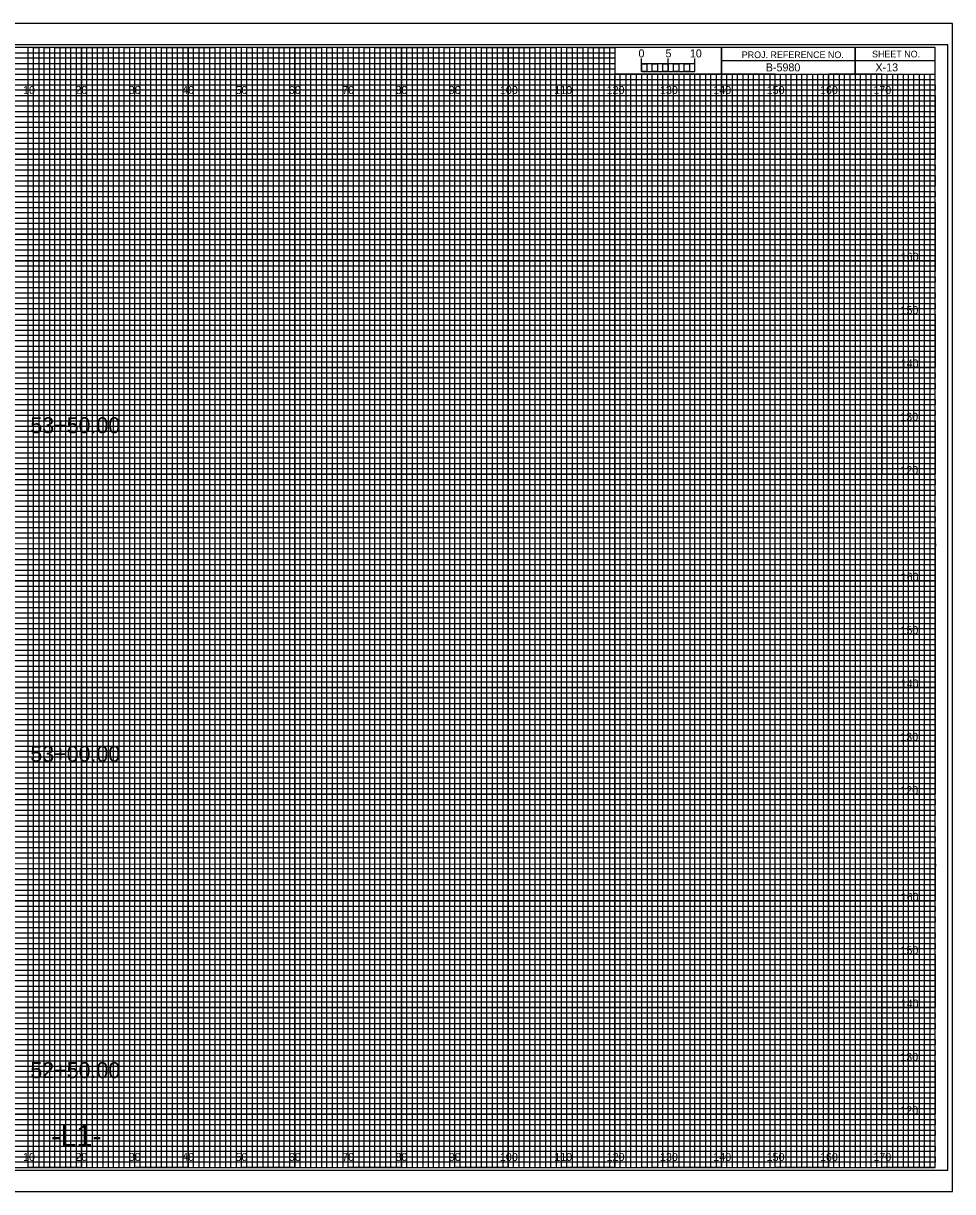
# Model space of a CAD drawing. Extents: x -13 to 323, y -5 to 3294.
# Drawn here: x 149.1 to 323.3, y 2635.5 to 2854.5 of the extents above; entities that cross this region are included whole.
import ezdxf

# ---------------------------------------------------------------- set-up
doc = ezdxf.new("R2010")
doc.units = 0
for name, color, linetype in [('Prop XS Alignment Label', 7, 'Continuous'), ('Prop XS Bar Scale Labels', 7, 'Continuous'), ('Prop XS Elevation Labels', 7, 'Continuous'), ('Prop XS Offset Labels', 7, 'Continuous'), ('Prop XS Project Number', 7, 'Continuous'), ('Prop XS Sheet Number', 7, 'Continuous'), ('Prop XS Station Labels', 7, 'Continuous'), ('Scratch_Level_0', 7, 'Continuous'), ('Sheet Cross Section CELL', 7, 'Continuous'), ('Sheet Cross Section Grid Major CELL', 7, 'Continuous'), ('Sheet Cross Section Grid Middle CELL', 7, 'Continuous'), ('Sheet Cross Section Grid Minor 1 CELL', 7, 'Continuous'), ('Sheet Cross Section Grid Minor 2 CELL', 7, 'Continuous'), ('Sheet Cross Section Scale CELL', 7, 'Continuous'), ('Sheet Cutting Line CELL', 7, 'Continuous'), ('Sheet DOT Grid CELL', 7, 'Continuous'), ('Sheet Plot Border Inside CELL', 7, 'Continuous'), ('Sheet Plot Border Outside CELL', 7, 'Continuous')]:
    doc.layers.add(name, color=color, linetype=linetype)

msp = doc.modelspace()

# ---------------------------------------------------------------- linework, layer by layer
at = {"layer": 'Scratch_Level_0'}
for points in [[(10, 2815), (310, 2815), (310, 2770), (10, 2770)], [(10, 2750), (320, 2750), (320, 2710), (10, 2710)], [(10, 2690), (310, 2690), (310, 2650), (10, 2650)]]:
    msp.add_lwpolyline(points, close=True, dxfattribs=at)
at = {"layer": 'Sheet Cross Section CELL'}
for p, q in [((305, 2850), (305, 2845)), ((305, 2845), (305, 2850)), ((280, 2847.5), (280, 2845)), ((320, 2847.49), (280, 2847.49)), ((280, 2845), (320, 2845))]:
    msp.add_line(p, q, dxfattribs=at)
for points in [[(320, 2850), (0, 2850), (0, 2640), (320, 2640)], [(280, 2850), (260, 2850), (260, 2845.03), (280, 2845.03)], [(320, 2850), (280, 2850), (280, 2845), (320, 2845)]]:
    msp.add_lwpolyline(points, close=True, dxfattribs=at)
at = {"layer": 'Sheet Cross Section Grid Major CELL'}
for p, q in [((150, 2850), (140, 2850)), ((150, 2640), (150, 2850)), ((170, 2850), (160, 2850)), ((160, 2850), (160, 2640)), ((170, 2640), (170, 2850)), ((190, 2850), (180, 2850)), ((180, 2850), (180, 2640)), ((190, 2640), (190, 2850)), ((210, 2850), (200, 2850)), ((200, 2850), (200, 2640)), ((210, 2640), (210, 2850)), ((230, 2850), (220, 2850)), ((220, 2850), (220, 2640)), ((230, 2640), (230, 2850)), ((250, 2850), (240, 2850)), ((240, 2850), (240, 2640)), ((250, 2640), (250, 2850)), ((260, 2850), (260, 2640)), ((270, 2640), (270, 2845)), ((290, 2845), (280, 2845)), ((280, 2845), (280, 2640)), ((290, 2640), (290, 2845)), ((310, 2845), (300, 2845)), ((300, 2845), (300, 2640)), ((310, 2640), (310, 2845)), ((160, 2640), (150, 2640)), ((180, 2640), (170, 2640)), ((200, 2640), (190, 2640)), ((220, 2640), (210, 2640)), ((240, 2640), (230, 2640)), ((260, 2640), (250, 2640)), ((280, 2640), (270, 2640)), ((300, 2640), (290, 2640)), ((320, 2640), (310, 2640)), ((320, 2640), (320, 2640))]:
    msp.add_line(p, q, dxfattribs=at)
for points in [[(0, 2840), (320, 2840), (320, 2830), (0, 2830)], [(0, 2820), (320, 2820), (320, 2810), (0, 2810)], [(0, 2800), (320, 2800), (320, 2790), (0, 2790)], [(0, 2780), (320, 2780), (320, 2770), (0, 2770)], [(0, 2760), (320, 2760), (320, 2750), (0, 2750)], [(0, 2740), (320, 2740), (320, 2730), (0, 2730)], [(0, 2720), (320, 2720), (320, 2710), (0, 2710)], [(0, 2700), (320, 2700), (320, 2690), (0, 2690)], [(0, 2680), (320, 2680), (320, 2670), (0, 2670)], [(0, 2660), (320, 2660), (320, 2650), (0, 2650)]]:
    msp.add_lwpolyline(points, dxfattribs=at)
at = {"layer": 'Sheet Cross Section Grid Middle CELL'}
for points in [[(145, 2640), (155, 2640), (155, 2850), (165, 2850), (165, 2640), (175, 2640), (175, 2850), (185, 2850), (185, 2640), (195, 2640), (195, 2850), (205, 2850), (205, 2640), (215, 2640), (215, 2850), (225, 2850), (225, 2640), (235, 2640), (235, 2850), (245, 2850), (245, 2640), (255, 2640), (255, 2850), (259.93, 2850), (260, 2850), (260, 2845), (264.99, 2845), (264.99, 2640), (275, 2640), (275, 2845), (285, 2845), (285, 2640), (295, 2640), (295, 2845), (305, 2845), (305, 2640), (315, 2640), (315, 2845)], [(0, 2845), (275, 2845)], [(0, 2825), (320, 2825), (320, 2835), (0, 2835)], [(0, 2805), (320, 2805), (320, 2815), (0, 2815)], [(0, 2785), (320, 2785), (320, 2795), (0, 2795)], [(0, 2765), (320, 2765), (320, 2775), (0, 2775)], [(0, 2745), (320, 2745), (320, 2755), (0, 2755)], [(0, 2725), (320, 2725), (320, 2735), (0, 2735)], [(0, 2705), (320, 2705), (320, 2715), (0, 2715)], [(0, 2685), (320, 2685), (320, 2695), (0, 2695)], [(0, 2665), (320, 2665), (320, 2675), (0, 2675)], [(0, 2645), (320, 2645), (320, 2655), (0, 2655)]]:
    msp.add_lwpolyline(points, dxfattribs=at)
at = {"layer": 'Sheet Cross Section Grid Minor 1 CELL'}
for p, q in [((0, 2849), (260, 2849)), ((260, 2847.98), (0, 2847.98)), ((0, 2847), (260, 2847)), ((260, 2849), (260, 2847.98)), ((260, 2847), (260, 2845.89)), ((260, 2845.89), (0, 2845.89)), ((0, 2844), (320, 2844))]:
    msp.add_line(p, q, dxfattribs=at)
for points in [[(0, 2843), (270, 2843), (320, 2843), (320, 2842), (0, 2842)], [(0, 2841), (320, 2841), (320, 2839), (0, 2839)], [(0, 2838), (320, 2838), (320, 2837), (0, 2836.98)], [(0, 2836), (320, 2836), (320, 2834), (0, 2834)], [(0, 2833), (320, 2833), (320, 2832), (0, 2832)], [(0, 2831), (320, 2831), (320, 2829), (0, 2829)], [(0, 2828), (320, 2828), (320, 2827), (0, 2827)], [(0, 2826), (320, 2826), (320, 2824), (0, 2824)], [(0, 2823), (320, 2823), (320, 2822), (0, 2822)], [(0, 2821), (320, 2821), (320, 2819), (0, 2819)], [(0, 2818), (320, 2818), (320, 2817), (0, 2817)], [(0, 2816), (320, 2816), (320, 2813.95), (320, 2813), (320, 2812), (0, 2812)], [(0, 2814), (320, 2814), (320, 2813), (0, 2813)], [(0, 2811), (320, 2811), (320, 2809), (0, 2809.03)], [(0, 2809.03), (320, 2809), (320, 2808), (0, 2808)], [(0, 2807), (320, 2807), (320, 2806), (0, 2806)], [(0, 2804), (320, 2804), (320, 2803), (0, 2803)], [(0, 2802), (320, 2802), (320, 2801), (0, 2801)], [(-0.07, 2798.89), (320, 2798.89), (320, 2797.88), (-0.07, 2797.88)], [(0, 2797), (320, 2797), (320, 2796), (0, 2796)], [(0, 2794), (320, 2794), (320, 2793), (0, 2793)], [(0, 2792), (320, 2792), (320, 2791), (0, 2791)], [(0, 2789), (320, 2789), (320, 2788), (0, 2788)], [(0, 2787), (320, 2787), (320, 2786), (0, 2786)], [(0, 2784), (320, 2784), (320, 2783), (0, 2783)], [(0, 2782), (320, 2782), (320, 2781), (0, 2781)], [(0, 2779), (320, 2779), (319.99, 2777.98), (0, 2778)], [(0, 2777), (320, 2777), (320, 2776), (0, 2776)], [(0, 2774), (320, 2774), (320, 2773), (0, 2773)], [(0, 2772), (320, 2772), (320, 2771), (0, 2771)], [(0, 2769), (320, 2769), (320, 2768), (0, 2768)], [(0, 2767), (320, 2767), (320, 2766), (0, 2766)], [(0, 2764), (320, 2764), (320, 2763), (0, 2763)], [(0, 2762), (320, 2762), (320, 2761), (0, 2761)], [(0, 2759), (320, 2759), (320, 2758), (0, 2758)], [(0, 2756.99), (320.07, 2756.91), (320, 2756), (0, 2756)], [(0, 2754), (320, 2754), (320, 2753), (0, 2753)], [(0, 2752), (320, 2752), (320, 2751), (0, 2751)], [(0, 2749), (320, 2749), (320, 2748), (0, 2748)], [(0, 2747), (320, 2747), (320, 2746), (0, 2746)], [(0, 2744), (320, 2744), (320, 2743), (0, 2743)], [(0, 2742), (320, 2742), (320, 2741), (0, 2741)], [(0, 2739), (320, 2739), (320, 2738), (0, 2738)], [(0, 2737), (320, 2737), (320, 2736), (0, 2736)], [(0, 2734), (320, 2734), (320, 2733), (0, 2733)], [(0, 2732), (320, 2732), (320, 2731), (0, 2731)], [(0, 2729), (320, 2729), (320, 2728), (0, 2728)], [(0, 2727), (320, 2727), (320, 2726), (0, 2726)], [(0, 2724), (320, 2724), (320, 2723), (0, 2723)], [(0, 2722), (320, 2722), (320, 2721), (0, 2721)], [(0, 2719), (320, 2719), (319.99, 2717.98), (0, 2718)], [(0, 2717), (320, 2717), (320, 2716), (0, 2716)], [(0, 2714), (320, 2714), (320, 2713), (0, 2713)], [(0, 2712), (320, 2712), (320, 2711), (0, 2711)], [(0, 2709), (320, 2709), (320, 2708), (0, 2708)], [(0, 2707), (320, 2707), (320, 2706), (0, 2706)], [(0, 2704), (320, 2704), (320, 2703), (0, 2703)], [(0, 2702), (320, 2702), (320, 2701), (0, 2701)], [(0, 2699), (320, 2699), (320, 2698), (0, 2698)], [(0, 2696.99), (320.07, 2696.91), (320, 2696), (0, 2696)], [(0, 2694), (320, 2694), (320, 2693), (0, 2693)], [(0, 2692), (320, 2692), (320, 2691), (0, 2691)], [(0, 2689), (320, 2689), (320, 2688), (0, 2688)], [(0, 2687), (320, 2687), (320, 2686), (0, 2686)], [(0, 2684), (320, 2684), (320, 2683), (0, 2683)], [(0, 2682), (320, 2682), (320, 2681), (0, 2681)], [(0, 2679), (320, 2679), (320, 2678), (0, 2678)], [(0, 2677), (320, 2677), (320, 2676), (0, 2676)], [(0, 2674), (320, 2674), (320, 2673), (0, 2673)], [(0, 2672), (320, 2672), (320, 2671), (0, 2671)], [(0, 2669), (320, 2669), (320, 2668), (0, 2668)], [(0, 2667), (320, 2667), (320, 2666), (0, 2666)], [(0, 2664), (320, 2664), (320, 2663), (0, 2663)], [(0, 2662), (320, 2662), (320, 2661), (0, 2661)], [(0, 2659), (320, 2659), (320, 2658), (0, 2658)], [(0, 2657), (320, 2657), (320, 2656), (0, 2656)], [(0, 2654), (320, 2654), (320, 2653), (0, 2653)], [(0, 2652), (320, 2652), (320, 2651), (0, 2651)], [(0, 2649), (320, 2649), (320, 2648), (0, 2648)], [(0, 2647), (320, 2647), (320, 2646), (0, 2646)], [(0, 2644), (320, 2644), (320, 2643), (0, 2643)], [(0, 2642), (320, 2642), (320, 2641), (0, 2641)]]:
    msp.add_lwpolyline(points, dxfattribs=at)
at = {"layer": 'Sheet Cross Section Grid Minor 2 CELL'}
for p, q in [((267, 2845), (266.01, 2845)), ((266.01, 2845), (266.01, 2640)), ((267, 2640), (267, 2845)), ((269, 2845), (268, 2845)), ((268, 2845), (268, 2640)), ((269, 2640), (269, 2845)), ((266.01, 2640), (265, 2640)), ((268, 2640), (267, 2640))]:
    msp.add_line(p, q, dxfattribs=at)
for points in [[(150, 2640), (151, 2640), (151, 2850), (152, 2850), (152, 2640)], [(152, 2640), (153, 2640), (153, 2850), (154, 2850), (154, 2640)], [(155, 2640), (156, 2640), (156, 2850), (157, 2850), (157, 2640)], [(157, 2640), (158, 2640), (158, 2850), (159, 2850), (159, 2640)], [(160, 2640), (161, 2640), (161, 2850), (162, 2850), (162, 2640)], [(162, 2640), (163, 2640), (163, 2850), (164, 2850), (164, 2640)], [(165, 2640), (166, 2640), (166, 2850), (167, 2850), (167, 2640)], [(167, 2640), (168, 2640), (168, 2850), (169, 2850), (169, 2640)], [(170, 2640), (171, 2640), (171, 2850), (172, 2850), (172, 2640)], [(172, 2640), (173, 2640), (173, 2850), (174, 2850), (174, 2640)], [(175, 2640), (176, 2640), (176, 2850), (177, 2850), (177, 2640)], [(177, 2640), (178, 2640), (178, 2850), (179, 2850), (179, 2640)], [(180, 2640), (181, 2640), (181, 2850), (182, 2850), (182, 2640)], [(182, 2640), (183, 2640), (183, 2850), (184, 2850), (184, 2640)], [(185, 2640), (186, 2640), (186, 2850), (187, 2850), (187, 2640)], [(187, 2640), (188, 2640), (188, 2850), (189, 2850), (189, 2640)], [(190, 2640), (191, 2640), (191, 2850), (192, 2850), (192, 2640)], [(192, 2640), (193, 2640), (193, 2850), (194, 2850), (194, 2640)], [(195, 2640), (196, 2640), (196, 2850), (197, 2850), (197, 2640)], [(197, 2640), (198, 2640), (198, 2850), (199, 2850), (199, 2640)], [(200, 2640), (201, 2640), (201, 2850), (202, 2850), (202, 2640)], [(202, 2640), (203, 2640), (203, 2850), (204, 2850), (204, 2640)], [(205, 2640), (206, 2640), (206, 2850), (207, 2850), (207, 2640)], [(207, 2640), (208, 2640), (208, 2850), (209, 2850), (209, 2640)], [(210, 2640), (211, 2640), (211, 2850), (212, 2850), (212, 2640)], [(212, 2640), (213, 2640), (213, 2850), (214, 2850), (214, 2640)], [(215, 2640), (216, 2640), (216, 2850), (217, 2850), (217, 2640)], [(217, 2640), (218, 2640), (218, 2850), (219, 2850), (219, 2640)], [(220, 2640), (221, 2640), (221, 2850), (222, 2850), (222, 2640)], [(222, 2640), (223, 2640), (223, 2850), (224, 2850), (224, 2640)], [(225, 2640), (226, 2640), (226, 2850), (227, 2850), (227, 2640)], [(227, 2640), (228, 2640), (228, 2850), (229, 2850), (229, 2640)], [(230, 2640), (231, 2640), (231, 2850), (232, 2850), (232, 2640)], [(232, 2640), (233, 2640), (233, 2850), (234, 2850), (234, 2640)], [(235, 2640), (236, 2640), (236, 2850), (237, 2850), (237, 2640)], [(237, 2640), (238, 2640), (238, 2850), (239, 2850), (239, 2640)], [(240, 2640), (241, 2640), (241, 2850), (242, 2850), (242, 2640)], [(242, 2640), (243, 2640), (243, 2850), (244, 2850), (244, 2640)], [(245, 2640), (246, 2640), (246, 2850), (247, 2850), (247, 2640)], [(247, 2640), (248, 2640), (248, 2850), (249, 2850), (249, 2640)], [(250, 2640), (251, 2640), (251, 2850), (252, 2850), (252, 2640)], [(252, 2640), (253, 2640), (253, 2850), (254, 2850), (254, 2640)], [(255, 2640), (256, 2640), (256, 2850), (257, 2850), (257, 2640)], [(257, 2640), (258, 2640), (258, 2850), (259, 2850), (259, 2640)], [(260, 2640), (261, 2640), (261, 2845), (262.02, 2845), (262.02, 2640)], [(262, 2640), (263, 2640), (263, 2845), (263.99, 2845), (263.99, 2640)], [(270, 2640), (270.98, 2640), (270.98, 2845), (272, 2845), (272, 2640)], [(272, 2640), (273, 2640), (273, 2845), (274.05, 2845), (274.05, 2640)], [(275, 2640), (276, 2640), (276, 2845), (277, 2845), (277, 2640)], [(277, 2640), (278, 2640), (278, 2845), (279, 2845), (279, 2640)], [(280, 2640), (281, 2640), (281, 2845), (282, 2845), (282, 2640)], [(282, 2640), (283, 2640), (283, 2845), (284, 2845), (284, 2640)], [(285, 2640), (286, 2640), (286, 2845), (287, 2845), (287, 2640)], [(287, 2640), (288, 2640), (288, 2845), (289, 2845), (289, 2640)], [(290, 2640), (291, 2640), (291, 2845), (292, 2845), (292, 2640)], [(292, 2640), (293, 2640), (293, 2845), (294, 2845), (294, 2640)], [(295, 2640), (296, 2640), (296, 2845), (297, 2845), (297, 2640)], [(297, 2640), (298, 2640), (298, 2845), (299, 2845), (299, 2640)], [(300, 2640), (301, 2640), (301, 2845), (302, 2845), (302, 2640)], [(302, 2640), (303, 2640), (303, 2845), (304, 2845), (304, 2640)], [(305, 2640), (306, 2640), (306, 2845), (307, 2845), (307, 2640)], [(307, 2640), (308, 2640), (308, 2845), (309, 2845), (309, 2640)], [(310, 2640), (311, 2640), (311, 2845), (312, 2845), (312, 2640)], [(312, 2640), (313, 2640), (313, 2845), (314, 2845), (314, 2640)], [(315, 2640), (316, 2640), (316, 2845), (317, 2845), (317, 2640)], [(317, 2640), (318, 2640), (318, 2845), (319, 2845), (319, 2640)]]:
    msp.add_lwpolyline(points, dxfattribs=at)
at = {"layer": 'Sheet Cross Section Scale CELL'}
for p, q in [((265, 2845.49), (265, 2847.9)), ((265, 2846.9), (265, 2847.9)), ((270, 2845.49), (270, 2847.9)), ((275, 2845.49), (275, 2847.9)), ((275, 2846.9), (275, 2847.9))]:
    msp.add_line(p, q, dxfattribs=at)
for points in [[(275, 2846.9), (265, 2846.9), (265, 2845.49), (275, 2845.49)], [(265, 2846.9), (266, 2846.9), (266, 2845.49), (265, 2845.49)], [(267, 2846.9), (268, 2846.9), (268, 2845.49), (267, 2845.49)], [(269, 2846.9), (270, 2846.9), (270, 2845.49), (269, 2845.49)], [(271, 2846.9), (272, 2846.9), (272, 2845.49), (271, 2845.49)], [(273, 2846.9), (274, 2846.9), (274, 2845.49), (273, 2845.49)]]:
    msp.add_lwpolyline(points, close=True, dxfattribs=at)
at = {"layer": 'Sheet Cutting Line CELL'}
for p, q in [((323.3, 2854.5), (-13.4, 2854.5)), ((-13.4, 2635.5), (323.3, 2635.5))]:
    msp.add_line(p, q, dxfattribs=at)
at = {"layer": 'Sheet DOT Grid CELL'}
for p, q in [((150, 2640), (150, 2850)), ((160, 2640), (160, 2850)), ((170, 2640), (170, 2850)), ((180, 2640), (180, 2850)), ((190, 2640), (190, 2850)), ((200, 2640), (200, 2850)), ((210, 2640), (210, 2850)), ((220, 2640), (220, 2850)), ((230, 2640), (230, 2850)), ((240, 2640), (240, 2850)), ((250, 2640), (250, 2850)), ((260, 2640), (260, 2844.69)), ((270, 2640), (270, 2844.69)), ((280, 2640), (280, 2844.69)), ((290, 2640), (290, 2844.69)), ((300, 2640), (300, 2844.69)), ((310, 2640), (310, 2844.69)), ((0, 2840), (320, 2840)), ((0, 2830), (320, 2830)), ((0, 2820), (320, 2820)), ((0, 2810), (320, 2810)), ((0, 2800), (320, 2800)), ((0, 2790), (320, 2790)), ((0, 2780), (320, 2780)), ((0, 2770), (320, 2770)), ((0, 2760), (320, 2760)), ((0, 2750), (320, 2750)), ((0, 2740), (320, 2740)), ((0, 2730), (320, 2730)), ((0, 2720), (320, 2720)), ((0, 2710), (320, 2710)), ((0, 2700), (320, 2700)), ((0, 2690), (320, 2690)), ((0, 2680), (320, 2680)), ((0, 2670), (320, 2670)), ((0, 2660), (320, 2660)), ((0, 2650), (320, 2650))]:
    msp.add_line(p, q, dxfattribs=at)
at = {"layer": 'Sheet Plot Border Inside CELL'}
msp.add_lwpolyline([(-10.8, 2639.5), (322.4, 2639.5), (322.4, 2850.5), (-10.8, 2850.5)], close=True, dxfattribs=at)
at = {"layer": 'Sheet Plot Border Outside CELL'}
msp.add_lwpolyline([(-13.4, 2635.5), (323.3, 2635.5), (323.3, 2854.5), (-13.4, 2854.5)], close=True, dxfattribs=at)

# ---------------------------------------------------------------- texts
at = {"layer": 'Prop XS Alignment Label'}
msp.add_text('-L1-', height=4, dxfattribs=at).set_placement((154.28, 2644))
at = {"layer": 'Prop XS Bar Scale Labels'}
for s, p in [('5', (269.47, 2848.12)), ('10', (274.04, 2848.12))]:
    msp.add_text(s, height=1.5, dxfattribs=at).set_placement(p)
at = {"layer": 'Prop XS Elevation Labels'}
for s, p in [('160', (313.57, 2810)), ('150', (313.52, 2800)), ('140', (313.57, 2790)), ('130', (313.49, 2780)), ('120', (313.5, 2770)), ('160', (313.57, 2750)), ('150', (313.52, 2740)), ('140', (313.57, 2730)), ('130', (313.49, 2720)), ('120', (313.5, 2710)), ('160', (313.57, 2690)), ('150', (313.52, 2680)), ('140', (313.57, 2670)), ('130', (313.49, 2660)), ('120', (313.5, 2650))]:
    msp.add_text(s, height=1.5, dxfattribs=at).set_placement(p)
at = {"layer": 'Prop XS Offset Labels'}
for s, p in [('10', (149.04, 2841.25)), ('20', (158.86, 2841.25)), ('30', (168.86, 2841.25)), ('40', (178.86, 2841.25)), ('50', (188.86, 2841.25)), ('60', (198.86, 2841.25)), ('70', (208.86, 2841.25)), ('80', (218.86, 2841.25)), ('90', (228.86, 2841.25)), ('100', (238.44, 2841.25)), ('110', (248.62, 2841.25)), ('120', (258.44, 2841.25)), ('130', (268.44, 2841.25)), ('140', (278.44, 2841.25)), ('150', (288.44, 2841.25)), ('160', (298.44, 2841.25)), ('170', (308.44, 2841.25)), ('10', (149.04, 2641.25)), ('20', (158.86, 2641.25)), ('30', (168.86, 2641.25)), ('40', (178.86, 2641.25)), ('50', (188.86, 2641.25)), ('60', (198.86, 2641.25)), ('70', (208.86, 2641.25)), ('80', (218.86, 2641.25)), ('90', (228.86, 2641.25)), ('100', (238.44, 2641.25)), ('110', (248.62, 2641.25)), ('120', (258.44, 2641.25)), ('130', (268.44, 2641.25)), ('140', (278.44, 2641.25)), ('150', (288.44, 2641.25)), ('160', (298.44, 2641.25)), ('170', (308.44, 2641.25))]:
    msp.add_text(s, height=1.5, dxfattribs=at).set_placement(p)
at = {"layer": 'Prop XS Project Number'}
msp.add_text('B-5980', height=1.5, dxfattribs=at).set_placement((288.28, 2845.5))
at = {"layer": 'Prop XS Sheet Number'}
msp.add_text('X-13', height=1.5, dxfattribs=at).set_placement((308.83, 2845.5))
at = {"layer": 'Prop XS Station Labels'}
for s, p in [('53+50.00', (150.41, 2777.66)), ('53+00.00', (150.41, 2716.08)), ('52+50.00', (150.41, 2656.78))]:
    msp.add_text(s, height=3, dxfattribs=at).set_placement(p)
at = {"layer": 'Sheet Cross Section CELL'}
for s, p in [('PROJ. REFERENCE NO.', (283.77, 2847.99)), ('SHEET NO.', (308.19, 2848.12))]:
    msp.add_text(s, height=1.25, dxfattribs=at).set_placement(p)
at = {"layer": 'Sheet Cross Section Scale CELL'}
msp.add_text('0', height=1.5, dxfattribs=at).set_placement((264.41, 2848.12))

doc.saveas('drawing.dxf')
